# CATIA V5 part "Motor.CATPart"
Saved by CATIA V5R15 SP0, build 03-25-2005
Part number: Motor
Material "Car Paint 2": density 7860 kg/m3, Young's modulus 2e+11 Pa, Poisson ratio 0.266
Bounding box of the stored display mesh (mm): x -158 to 158, y -158 to 158, z -192.059 to 130.141
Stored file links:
  E:\#01 CATIA Lecture Materials\#06 DMU\#11 DMU Page01 KIN EX11\Motor.CATPart
  C:\Program Files\Dassault Systemes\B20\win_b64\startup\materials\Catalog.CATMaterial
  E:\users\ast\Adele\Cxr14\Material_R14\Material\CNext\startup\materials\shaders\car_paint.isl
  dark_noise.bw
  exterior.rgb
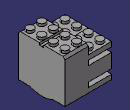
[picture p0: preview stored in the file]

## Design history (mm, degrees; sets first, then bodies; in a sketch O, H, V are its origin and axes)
Body1 (main body), material "Car Paint 2"
  Sketch1 on yz-plane, origin (0, 0, 0), H (0, 1, 0), V (0, 0, 1)
    point P1 (-158, 98.799)
    line L1 (-158, 98.799) -> (-143.8579, 112.9412)
    point P2 (-143.8579, 112.9412)
    line L2 (-143.8579, 112.9412) -> (-15, 112.9412)
    point P3 (-15, 112.9412)
    line L3 (-15, 112.9412) -> (-15, 97.9412)
    point P4 (-15, 97.9412)
    line L4 (-15, 97.9412) -> (0, 97.9412)
    point P5 (0, 97.9412)
    line L5 (-158, 98.799) -> (-158, -175.0588)
    point P6 (-158, -175.0588)
    line L6 (-158, -175.0588) -> (-79, -175.0588)
    point P7 (-79, -175.0588)
    arc A1 centre (0, 0) radius 192.0588 from (-79, -175.0588) to (0, -192.0588) ccw
    point P8 (0, 0)
    point P9 (0, -192.0588)
    point P10 (15, 112.9412)
    point P11 (143.8579, 112.9412)
    line L7 (143.8579, 112.9412) -> (15, 112.9412)
    point P12 (158, 98.799)
    line L8 (158, 98.799) -> (143.8579, 112.9412)
    point P13 (158, -175.0588)
    line L9 (158, 98.799) -> (158, -175.0588)
    point P14 (79, -175.0588)
    line L10 (158, -175.0588) -> (79, -175.0588)
    point P15 (0, -192.0588)
    arc A2 centre (0, 0) radius 192.0588 from (79, -175.0588) to (0, -192.0588) cw
    point P17 (15, 97.9412)
    line L11 (15, 112.9412) -> (15, 97.9412)
    point P18 (0, 97.9412)
    line L12 (15, 97.9412) -> (0, 97.9412)
    distance L6 L2 = 288
    length L6 = 79
    distance L5 V = 158
    distance L3 V = 15
    distance L4 L2 = 15
    length L1 = 20
    angle L1 L5 = 45
    distance L2 P9 = 305
    horizontal: L2 H, L4 H, L6 H
    vertical: L3 V, L5 V
    coincidence: P5 V, P9 V, P8 O, P5 P18, P9 P15
    symmetry: P3 P10 V, P2 P11 V, L2 L7 V, P1 P12 V, L1 L8 V, P6 P13 V, L5 L9 V, P7 P14 V, L6 L10 V, P9 P15 V, A1 A2 V, P4 P17 V, L3 L11 V, P5 P18 V, L4 L12 V
  Pad1: profile Sketch1, direction (1, 0, 0), length 158
  Sketch2 on yz-plane, origin (0, 0, 0), H (0, 1, 0), V (0, 0, 1)
    point P1 (0, 48.9412)
    line L1 (0, 48.9412) -> (-158, 48.9412)
    point P2 (-158, 48.9412)
    line L2 (-158, 48.9412) -> (-158, 16.9412)
    point P3 (-158, 16.9412)
    line L3 (-158, 16.9412) -> (-122.5, 16.9412)
    point P4 (-122.5, 16.9412)
    line L4 (-122.5, 16.9412) -> (-122.5, -15.0588)
    point P5 (-122.5, -15.0588)
    line L5 (-122.5, -15.0588) -> (-158, -15.0588)
    point P6 (-158, -15.0588)
    line L6 (-158, -15.0588) -> (-158, -111.0588)
    point P7 (-158, -111.0588)
    line L7 (-158, -111.0588) -> (-122.5, -111.0588)
    point P8 (-122.5, -111.0588)
    line L8 (-122.5, -111.0588) -> (-122.5, -143.0588)
    point P9 (-122.5, -143.0588)
    line L9 (-122.5, -143.0588) -> (-158, -143.0588)
    point P10 (-158, -143.0588)
    line L10 (-158, -143.0588) -> (-158, -175.0588)
    point P11 (-158, -175.0588)
    line L11 (-158, -175.0588) -> (0, -175.0588)
    point P12 (0, -175.0588)
    reference projected line E1 (-158, 98.799) -> (-158, -175.0588) from edge [face of Pad1 from Sketch1.L5 | end face of Pad1]
    reference projected line E2 (-15, 112.9412) -> (-143.8579, 112.9412) from edge [face of Pad1 from Sketch1.L2 | end face of Pad1]
    reference projected line E3 (-158, -175.0588) -> (-79, -175.0588) from edge [face of Pad1 from Sketch1.L6 | end face of Pad1]
    point P13 (0, 0)
    point P14 (0, 48.9412)
    point P15 (158, 48.9412)
    point P16 (158, 16.9412)
    point P17 (122.5, 16.9412)
    point P18 (122.5, -15.0588)
    point P19 (158, -15.0588)
    point P20 (158, -111.0588)
    point P21 (122.5, -111.0588)
    point P22 (122.5, -143.0588)
    point P23 (158, -143.0588)
    point P24 (158, -175.0588)
    point P25 (0, -175.0588)
    line L12 (0, 48.9412) -> (158, 48.9412)
    line L13 (158, 48.9412) -> (158, 16.9412)
    line L14 (158, 16.9412) -> (122.5, 16.9412)
    line L15 (122.5, 16.9412) -> (122.5, -15.0588)
    line L16 (122.5, -15.0588) -> (158, -15.0588)
    line L17 (158, -15.0588) -> (158, -111.0588)
    line L18 (158, -111.0588) -> (122.5, -111.0588)
    line L19 (122.5, -111.0588) -> (122.5, -143.0588)
    line L20 (122.5, -143.0588) -> (158, -143.0588)
    line L21 (158, -143.0588) -> (158, -175.0588)
    line L22 (158, -175.0588) -> (0, -175.0588)
    distance L4 V = 122.5
    distance L1 E2 = 64
    distance L3 L1 = 32
    distance L9 L11 = 32
    length L4 = 32
    length L8 = 32
    coincidence: P1 V, P6 L2, P8 L4, P10 L2, P12 V, L2 E1, L11 E3, P1 P14, P12 P25
    horizontal: L1 H, L3 H, L5 H, L7 H, L9 H, L11 H
    vertical: L2 V, L4 V, L6 V, L8 V, L10 V
    symmetry: O P13 V, P1 P14 V, P2 P15 V, P3 P16 V, P4 P17 V, P5 P18 V, P6 P19 V, P7 P20 V, P8 P21 V, P9 P22 V, P10 P23 V, P11 P24 V, P12 P25 V, L1 L12 V, L2 L13 V, L3 L14 V, L4 L15 V, L5 L16 V, L6 L17 V, L7 L18 V, L8 L19 V, L9 L20 V, L10 L21 V, L11 L22 V
  Pad2: profile Sketch2, direction (-1, 0, 0), length 158
  Sketch3 on face of Pad1 from Sketch1.L7, origin (0, 0, 112.9412), H (1, 0, 0), V (0, 1, 0)
    circle A1 centre (118.5, -118.5) radius 24.5
    point P1 (118.5, -118.5)
    reference projected line E1 (0, -158) -> (158, -158) from edge [face of Pad1 from Sketch1.L5 | face of Pad1 from Sketch1.L1]
    reference projected line E2 (158, -15) -> (158, -143.8579) from edge [face of Pad1 from Sketch1.L2 | end face of Pad1]
    radius A1 = 24.5
    distance P1 E1 = 39.5
    distance P1 E2 = 39.5
  Pad3: profile Sketch3, direction (0, 0, 1), length 17.2
  RectPattern1: of Pad3, direction 1 instances 2, spacing 79, along edge [face of Pad1 from Sketch1.L5 | face of Pad1 from Sketch1.L1] reversed
  Sketch4 on face of Pad2 from Sketch2.L1, origin (0, 0, 48.9412), H (1, 0, 0), V (0, 1, 0)
    circle A1 centre (-118.5, -118.5) radius 24.5
    point P1 (-118.5, -118.5)
    reference projected line E1 (0, -158) -> (-158, -158) from edge [face of Pad2 from Sketch2.L1 | face of Pad2]
    reference projected line E2 (-158, 0) -> (-158, -158) from edge [end face of Pad2 | face of Pad2 from Sketch2.L1]
    radius A1 = 24.5
    distance P1 E1 = 39.5
    distance P1 E2 = 39.5
  Pad4: profile Sketch4, direction (0, 0, 1), length 17.2
  RectPattern2: of Pad4, direction 1 instances 2, spacing 79, along edge [face of Pad2 from Sketch2.L1 | face of Pad2] reversed
  RectPattern3: of RectPattern2, direction 1 instances 4, spacing 79, along edge [end face of Pad2 | face of Pad2 from Sketch2.L12] reversed
  RectPattern4: of RectPattern1, direction 1 instances 4, spacing 79, along edge [face of Pad1 from Sketch1.L2 | end face of Pad1] reversed
  Sketch5 on face of Pad2, origin (0, 0, -175.0588), H (1, 0, 0), V (0, -1, 0)
    point P1 (0, 143)
    line L1 (0, 143) -> (143, 143)
    line L2 (143, 143) -> (143, 94)
    line L3 (143, 94) -> (0, 94)
    line L4 (0, 94) -> (0, 143)
    point P2 (143, 143)
    point P3 (143, 94)
    point P4 (0, 94)
    reference projected line E1 (158, 158) -> (158, 79) from edge [face of Pad2 | end face of Pad1]
    reference projected line E2 (0, 158) -> (158, 158) from edge [face of Pad2 | face of Pad2]
    reference projected line E3 (0, 79) -> (158, 79) from edge [face of Pad1 from Sketch1.A1 | face of Pad2]
    reference projected line E4 (0, 79) -> (0, 0) from edge [start face of Pad1 | face of Pad1 from Sketch1.A1]
    point P5 (-143, 143)
    line L5 (-143, 143) -> (-15, 143)
    line L6 (-15, 143) -> (-15, -143)
    line L7 (-15, -143) -> (-143, -143)
    line L8 (-143, -143) -> (-143, 143)
    reference projected line E5 (0, 79) -> (0, 0) from edge [start face of Pad1 | face of Pad1 from Sketch1.A1]
    reference projected line E6 (-158, 158) -> (-158, 0) from edge [end face of Pad2 | face of Pad2]
    reference projected line E7 (0, -158) -> (158, -158) from edge [face of Pad2 | face of Pad2]
    point P9 (0, -94)
    point P10 (143, -94)
    line L9 (143, -94) -> (0, -94)
    point P11 (143, -143)
    line L10 (143, -143) -> (143, -94)
    point P12 (0, -143)
    line L11 (0, -143) -> (143, -143)
    line L12 (0, -94) -> (0, -143)
    distance L2 E1 = 15
    distance L1 E2 = 15
    distance L3 E3 = 15
    distance L4 E4 = 0
    distance L6 E5 = 15
    distance L8 E6 = 15
    distance L7 E7 = 15
    horizontal: L1 H, L3 H, L5 H, L7 H
    vertical: L2 V, L4 V, L6 V, L8 V
    coincidence: P5 L1
    symmetry: P4 P9 H, P3 P10 H, L3 L9 H, P2 P11 H, L2 L10 H, P1 P12 H, L1 L11 H, L4 L12 H
  Pocket1: profile Sketch5, direction (0, 0, 1), length 17.2
  Sketch6 on end face of Pad2, origin (-158, 0, 0), H (0, -1, 0), V (0, 0, 1)
    circle A1 centre (0, -52.8088) radius 25.75
    point P1 (0, -52.8088)
    reference projected line E1 (158, -175.0588) -> (0, -175.0588) from edge [end face of Pad2 | face of Pad2]
    radius A1 = 25.75
    distance A1 E1 = 148
    coincidence: P1 V
  Pocket2: profile Sketch6, direction (1, 0, 0), length 50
